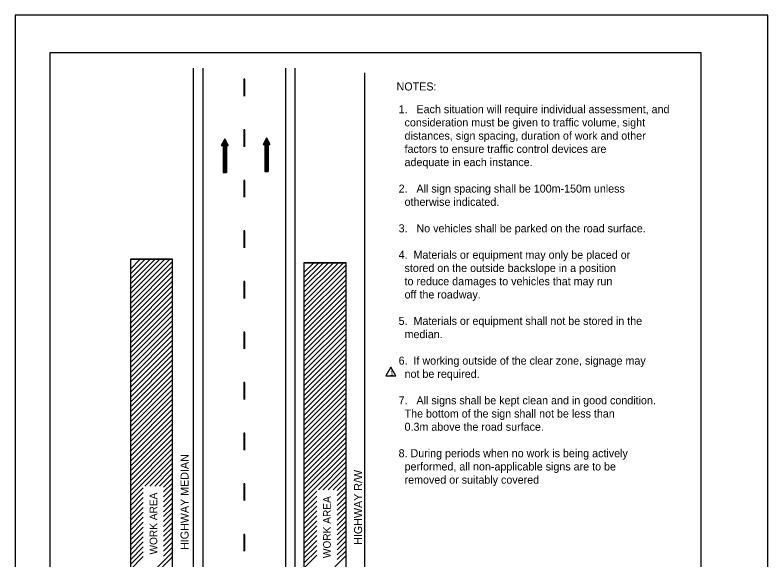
# Model space of a CAD drawing. Extents: x 1351 to 1567, y 178 to 457.
# Drawn here: x 1351.4 to 1567.4, y 300.5 to 456.9 of the extents above; entities that cross this region are included whole.
import ezdxf

# ---------------------------------------------------------------- set-up
doc = ezdxf.new("R2010")
doc.units = 0
for name, color, linetype in [('Level 1', 7, 'Continuous'), ('Level 10', 7, 'Continuous'), ('Level 2', 7, 'Continuous'), ('Level 60', 7, 'Continuous')]:
    doc.layers.add(name, color=color, linetype=linetype)

msp = doc.modelspace()

# ---------------------------------------------------------------- linework, layer by layer
at = {"layer": 'Level 1'}
msp.add_lwpolyline([(1459.19, 355.84), (1457.77, 353.37), (1460.61, 353.37)], close=True, dxfattribs=at)
at = {"layer": 'Level 10'}
for p, q in [((1402.52, 441.71), (1402.52, 425.37)), ((1405.24, 441.71), (1405.24, 425.37)), ((1428.95, 441.71), (1428.95, 425.37)), ((1431.69, 441.71), (1431.69, 425.37)), ((1451.69, 440.38), (1451.69, 195.81)), ((1402.52, 437.4), (1402.52, 437.4)), ((1402.52, 425.37), (1402.52, 373)), ((1405.24, 425.37), (1405.24, 373)), ((1428.95, 425.37), (1428.95, 373)), ((1431.69, 425.37), (1431.69, 373)), ((1411.55, 421.41), (1410.58, 419.48)), ((1411.55, 421.41), (1411.55, 411.74)), ((1411.55, 421.41), (1412.52, 419.48)), ((1423.57, 421.7), (1422.6, 419.76)), ((1423.33, 421.21), (1423.33, 412.02)), ((1423.45, 421.45), (1423.45, 412.02)), ((1423.57, 421.7), (1423.57, 412.02)), ((1423.57, 421.7), (1424.54, 419.76)), ((1423.69, 421.45), (1423.69, 412.02)), ((1423.81, 421.21), (1423.81, 412.02)), ((1410.58, 419.48), (1411.07, 419.48)), ((1410.7, 419.72), (1410.7, 419.48)), ((1410.83, 419.96), (1410.83, 419.48)), ((1410.95, 420.2), (1410.95, 419.48)), ((1411.07, 420.44), (1411.07, 411.74)), ((1411.07, 419.48), (1411.07, 411.74)), ((1411.19, 420.69), (1411.19, 411.74)), ((1411.31, 420.93), (1411.31, 411.74)), ((1411.43, 421.17), (1411.43, 411.74)), ((1411.67, 421.17), (1411.67, 411.74)), ((1411.79, 420.93), (1411.79, 411.74)), ((1411.91, 420.69), (1411.91, 411.74)), ((1412.04, 420.44), (1412.04, 411.74)), ((1412.04, 419.48), (1412.04, 411.74)), ((1412.04, 419.48), (1412.52, 419.48)), ((1412.16, 420.2), (1412.16, 419.48)), ((1412.28, 419.96), (1412.28, 419.48)), ((1412.4, 419.72), (1412.4, 419.48)), ((1422.6, 419.76), (1423.09, 419.76)), ((1422.73, 420), (1422.73, 419.76)), ((1422.85, 420.25), (1422.85, 419.76)), ((1422.97, 420.49), (1422.97, 419.76)), ((1423.09, 420.73), (1423.09, 412.02)), ((1423.09, 419.76), (1423.09, 412.02)), ((1423.21, 420.97), (1423.21, 412.02)), ((1423.93, 420.97), (1423.93, 412.02)), ((1424.06, 420.73), (1424.06, 412.02)), ((1424.06, 419.76), (1424.06, 412.02)), ((1424.06, 419.76), (1424.54, 419.76)), ((1424.18, 420.49), (1424.18, 419.76)), ((1424.3, 420.25), (1424.3, 419.76)), ((1424.42, 420), (1424.42, 419.76)), ((1411.07, 411.74), (1412.04, 411.74)), ((1423.09, 412.02), (1424.06, 412.02)), ((1384.5, 384.03), (1387.33, 386.86)), ((1384.5, 382.62), (1388.75, 386.86)), ((1384.5, 381.2), (1390.16, 386.86)), ((1384.5, 379.79), (1391.57, 386.86)), ((1384.5, 378.38), (1392.99, 386.86)), ((1384.5, 376.96), (1394.4, 386.86)), ((1384.5, 375.55), (1395.82, 386.86)), ((1384.5, 374.13), (1396.6, 386.23)), ((1384.5, 372.72), (1396.6, 384.81)), ((1434.29, 383.01), (1437.12, 385.84)), ((1434.29, 381.6), (1438.53, 385.84)), ((1434.29, 380.18), (1439.94, 385.84)), ((1434.29, 378.77), (1441.36, 385.84)), ((1434.29, 377.35), (1442.77, 385.84)), ((1434.29, 375.94), (1444.19, 385.84)), ((1434.29, 374.53), (1445.6, 385.84)), ((1434.29, 373.11), (1446.38, 385.21)), ((1384.5, 371.31), (1396.6, 383.4)), ((1434.29, 371.7), (1446.38, 383.79)), ((1434.29, 370.28), (1446.38, 382.38)), ((1384.5, 369.89), (1396.6, 381.99)), ((1384.5, 368.48), (1396.6, 380.57)), ((1434.29, 368.87), (1446.38, 380.96)), ((1384.5, 367.06), (1396.6, 379.16)), ((1434.29, 367.45), (1446.38, 379.55)), ((1434.29, 366.04), (1446.38, 378.13)), ((1384.5, 365.65), (1396.6, 377.74)), ((1384.5, 364.23), (1396.6, 376.33)), ((1434.29, 364.63), (1446.38, 376.72)), ((1384.5, 362.82), (1396.6, 374.91)), ((1434.29, 363.21), (1446.38, 375.31)), ((1434.29, 361.8), (1446.38, 373.89)), ((1384.5, 361.41), (1396.6, 373.5)), ((1384.5, 359.99), (1396.6, 372.09)), ((1402.52, 373), (1402.52, 195.81)), ((1405.24, 373), (1405.24, 195.81)), ((1428.95, 373), (1428.95, 195.81)), ((1431.69, 373), (1431.69, 195.81)), ((1434.29, 360.38), (1446.38, 372.48)), ((1384.5, 358.58), (1396.6, 370.67)), ((1434.29, 358.97), (1446.38, 371.06)), ((1434.29, 357.56), (1446.38, 369.65)), ((1384.5, 357.16), (1396.6, 369.26)), ((1384.5, 355.75), (1396.6, 367.84)), ((1434.29, 356.14), (1446.38, 368.24)), ((1384.5, 354.33), (1396.6, 366.43)), ((1434.29, 354.73), (1446.38, 366.82)), ((1434.29, 353.31), (1446.38, 365.41)), ((1384.5, 352.92), (1396.6, 365.01)), ((1384.5, 351.51), (1396.6, 363.6)), ((1434.29, 351.9), (1446.38, 363.99)), ((1384.5, 350.09), (1396.6, 362.19)), ((1384.5, 348.68), (1396.6, 360.77)), ((1434.29, 350.48), (1446.38, 362.58)), ((1434.29, 349.07), (1446.38, 361.16)), ((1384.5, 347.26), (1396.6, 359.36)), ((1434.29, 347.66), (1446.38, 359.75)), ((1384.5, 345.85), (1396.6, 357.94)), ((1384.5, 344.44), (1396.6, 356.53)), ((1434.29, 346.24), (1446.38, 358.34)), ((1434.29, 344.83), (1446.38, 356.92)), ((1384.5, 343.02), (1396.6, 355.12)), ((1434.29, 343.41), (1446.38, 355.51)), ((1384.5, 341.61), (1396.6, 353.7)), ((1384.5, 340.19), (1396.6, 352.29)), ((1434.29, 342), (1446.38, 354.09)), ((1434.29, 340.58), (1446.38, 352.68)), ((1384.5, 338.78), (1396.6, 350.87)), ((1434.29, 339.17), (1446.38, 351.26)), ((1384.5, 337.36), (1396.6, 349.46)), ((1384.5, 335.95), (1396.6, 348.04)), ((1434.29, 337.76), (1446.38, 349.85)), ((1434.29, 336.34), (1446.38, 348.44)), ((1384.5, 334.54), (1396.6, 346.63)), ((1434.29, 334.93), (1446.38, 347.02)), ((1434.29, 333.51), (1446.38, 345.61)), ((1384.5, 333.12), (1396.6, 345.22)), ((1384.5, 331.71), (1396.6, 343.8)), ((1434.29, 332.1), (1446.38, 344.19)), ((1384.5, 330.29), (1396.6, 342.39)), ((1434.29, 330.69), (1446.38, 342.78)), ((1434.29, 329.27), (1446.38, 341.37)), ((1384.5, 328.88), (1396.6, 340.97)), ((1384.5, 327.46), (1396.6, 339.56)), ((1434.29, 327.86), (1446.38, 339.95)), ((1384.5, 326.05), (1396.6, 338.14)), ((1434.29, 326.44), (1446.38, 338.54)), ((1434.29, 325.03), (1446.38, 337.12)), ((1384.5, 324.64), (1396.6, 336.73)), ((1384.5, 323.22), (1396.6, 335.32)), ((1434.29, 323.61), (1446.38, 335.71)), ((1384.5, 321.81), (1396.6, 333.9)), ((1434.29, 322.2), (1446.38, 334.29)), ((1434.29, 320.79), (1446.38, 332.88)), ((1384.5, 320.39), (1396.6, 332.49)), ((1384.5, 318.98), (1396.6, 331.07)), ((1434.29, 319.37), (1446.38, 331.47)), ((1388.65, 321.71), (1396.6, 329.66)), ((1434.29, 317.96), (1446.38, 330.05)), ((1438.44, 320.69), (1446.38, 328.64)), ((1390.07, 321.71), (1396.6, 328.25)), ((1391.48, 321.71), (1396.6, 326.83)), ((1439.85, 320.69), (1446.38, 327.22)), ((1392.89, 321.71), (1396.6, 325.42)), ((1394.03, 321.44), (1396.6, 324)), ((1441.27, 320.69), (1446.38, 325.81)), ((1442.68, 320.69), (1446.38, 324.39)), ((1394.03, 320.03), (1396.6, 322.59)), ((1443.82, 320.42), (1446.38, 322.98)), ((1384.5, 317.56), (1388.2, 321.26)), ((1384.5, 316.15), (1388.2, 319.85)), ((1394.03, 318.61), (1396.6, 321.17)), ((1394.03, 317.2), (1396.6, 319.76)), ((1434.29, 316.54), (1437.98, 320.24)), ((1443.82, 319), (1446.38, 321.57)), ((1443.82, 317.59), (1446.38, 320.15)), ((1384.5, 314.74), (1388.2, 318.43)), ((1394.03, 315.78), (1396.6, 318.35)), ((1434.29, 315.13), (1437.98, 318.82)), ((1443.82, 316.18), (1446.38, 318.74)), ((1384.5, 313.32), (1388.2, 317.02)), ((1384.5, 311.91), (1388.2, 315.61)), ((1394.03, 314.37), (1396.6, 316.93)), ((1394.03, 312.95), (1396.6, 315.52)), ((1434.29, 313.71), (1437.98, 317.41)), ((1434.29, 312.3), (1437.98, 316)), ((1443.82, 314.76), (1446.38, 317.32)), ((1443.82, 313.35), (1446.38, 315.91)), ((1384.5, 310.49), (1388.2, 314.19)), ((1394.03, 311.54), (1396.6, 314.1)), ((1434.29, 310.89), (1437.98, 314.58)), ((1443.82, 311.93), (1446.38, 314.5)), ((1384.5, 309.08), (1388.2, 312.78)), ((1384.5, 307.67), (1388.2, 311.36)), ((1394.03, 310.13), (1396.6, 312.69)), ((1394.03, 308.71), (1396.6, 311.28)), ((1434.29, 309.47), (1437.98, 313.17)), ((1434.29, 308.06), (1437.98, 311.75)), ((1443.82, 310.52), (1446.38, 313.08)), ((1443.82, 309.1), (1446.38, 311.67)), ((1384.5, 306.25), (1388.2, 309.95)), ((1394.03, 307.3), (1396.6, 309.86)), ((1434.29, 306.64), (1437.98, 310.34)), ((1434.29, 305.23), (1437.98, 308.93)), ((1443.82, 307.69), (1446.38, 310.25)), ((1384.5, 304.84), (1388.2, 308.53)), ((1384.5, 303.42), (1388.2, 307.12)), ((1394.03, 305.88), (1396.6, 308.45)), ((1394.03, 304.47), (1396.6, 307.03)), ((1434.29, 303.81), (1437.98, 307.51)), ((1443.82, 306.28), (1446.38, 308.84)), ((1443.82, 304.86), (1446.38, 307.42)), ((1384.5, 302.01), (1388.2, 305.7)), ((1394.03, 303.06), (1396.6, 305.62)), ((1434.29, 302.4), (1437.98, 306.1)), ((1434.29, 300.99), (1437.98, 304.68)), ((1443.82, 303.45), (1446.38, 306.01)), ((1443.82, 302.03), (1446.38, 304.6)), ((1384.5, 300.59), (1388.2, 304.29)), ((1384.5, 299.18), (1388.2, 302.88)), ((1384.5, 290.69), (1396.6, 302.79)), ((1394.03, 301.64), (1396.6, 304.2)), ((1434.29, 299.57), (1437.98, 303.27)), ((1443.82, 300.62), (1446.38, 303.18)), ((1384.5, 297.77), (1388.2, 301.46)), ((1384.5, 289.28), (1396.6, 301.38)), ((1434.29, 298.16), (1437.98, 301.86)), ((1434.29, 289.67), (1446.38, 301.77))]:
    msp.add_line(p, q, dxfattribs=at)
at = {"layer": 'Level 2'}
for p, q in [((1417.04, 438.49), (1417.04, 433.65)), ((1417.33, 438.49), (1417.04, 438.49)), ((1417.33, 433.65), (1417.33, 438.49)), ((1417.04, 423.98), (1417.04, 419.14)), ((1417.33, 423.98), (1417.04, 423.98)), ((1417.33, 419.14), (1417.33, 423.98)), ((1417.04, 409.46), (1417.04, 404.62)), ((1417.33, 409.46), (1417.04, 409.46)), ((1417.33, 404.62), (1417.33, 409.46)), ((1417.04, 394.95), (1417.04, 390.11)), ((1417.33, 394.95), (1417.04, 394.95)), ((1417.33, 390.11), (1417.33, 394.95)), ((1417.04, 380.43), (1417.04, 375.6)), ((1417.33, 380.43), (1417.04, 380.43)), ((1417.33, 375.6), (1417.33, 380.43)), ((1417.04, 365.92), (1417.04, 361.08)), ((1417.33, 365.92), (1417.04, 365.92)), ((1417.33, 361.08), (1417.33, 365.92)), ((1417.04, 351.41), (1417.04, 346.57)), ((1417.33, 351.41), (1417.04, 351.41)), ((1417.33, 346.57), (1417.33, 351.41)), ((1417.04, 336.89), (1417.04, 332.05)), ((1417.33, 336.89), (1417.04, 336.89)), ((1417.33, 332.05), (1417.33, 336.89)), ((1417.04, 322.38), (1417.04, 317.54)), ((1417.33, 322.38), (1417.04, 322.38)), ((1417.33, 317.54), (1417.33, 322.38)), ((1417.04, 307.86), (1417.04, 303.03)), ((1417.33, 307.86), (1417.04, 307.86)), ((1417.33, 303.03), (1417.33, 307.86))]:
    msp.add_line(p, q, dxfattribs=at)
at = {"layer": 'Level 60'}
for p, q in [((1567.41, 456.92), (1567.41, 456.92)), ((1384.5, 386.86), (1396.6, 386.86)), ((1434.29, 385.84), (1446.38, 385.84))]:
    msp.add_line(p, q, dxfattribs=at)
for points in [[(1567.41, 456.92), (1351.41, 456.92), (1351.41, 177.92), (1567.41, 177.92)], [(1548.28, 446.11), (1361.41, 446.11), (1361.41, 188.73), (1548.28, 188.73)], [(1396.6, 386.86), (1384.5, 386.86), (1384.5, 235.92), (1396.6, 235.92)], [(1446.38, 385.84), (1434.29, 385.84), (1434.29, 234.9), (1446.38, 234.9)]]:
    msp.add_lwpolyline(points, close=True, dxfattribs=at)

# ---------------------------------------------------------------- texts
at = {"layer": 'Level 1'}
msp.add_text('1', height=1.45, rotation=360, dxfattribs=at).set_placement((1458.96, 353.43))
at = {"layer": 'Level 10'}
for s, p in [('NOTES:', (1460.87, 435.27)), ('1.   Each situation will require individual assessment, and', (1461.45, 428.75)), ('  consideration must be given to traffic volume, sight', (1461.45, 424.95)), ('  distances, sign spacing, duration of work and other', (1461.45, 421.15)), ('  factors to ensure traffic control devices are', (1461.45, 417.35)), ('  adequate in each instance.', (1461.45, 413.56)), ('2.   All sign spacing shall be 100m-150m unless', (1461.45, 405.96)), ('  otherwise indicated.', (1461.45, 402.16)), ('3.   No vehicles shall be parked on the road surface.', (1461.45, 394.56)), ('4.  Materials or equipment may only be placed or', (1461.45, 386.97)), ('  stored on the outside backslope in a position', (1461.45, 383.17)), ('  to reduce damages to vehicles that may run', (1461.45, 379.37)), ('  off the roadway.', (1461.45, 375.57)), ('5.  Materials or equipment shall not be stored in the', (1461.45, 367.98)), ('  median. ', (1461.45, 364.18)), ('6.  If working outside of the clear zone, signage may ', (1461.45, 356.58)), ('  not be required.', (1461.45, 352.79)), ('7.   All signs shall be kept clean and in good condition.', (1461.45, 345.19)), ('  The bottom of the sign shall not be less than', (1461.45, 341.39)), ('  0.3m above the road surface.', (1461.45, 337.6)), ('8. During periods when no work is being actively', (1461.45, 330)), ('  performed, all non-applicable signs are to be', (1461.45, 326.2)), ('  removed or suitably covered', (1461.45, 322.4))]:
    msp.add_text(s, height=2.298, dxfattribs=at).set_placement(p)
for s, height, p in [('HIGHWAY MEDIAN', 2.298, (1401.18, 303.39)), ('HIGHWAY R/W', 2.298, (1450.97, 304.85)), ('WORK AREA', 2.177, (1392.2, 302.06)), ('WORK AREA', 2.177, (1441.98, 301.04))]:
    msp.add_text(s, height=height, rotation=90, dxfattribs=at).set_placement(p)

doc.saveas('drawing.dxf')
